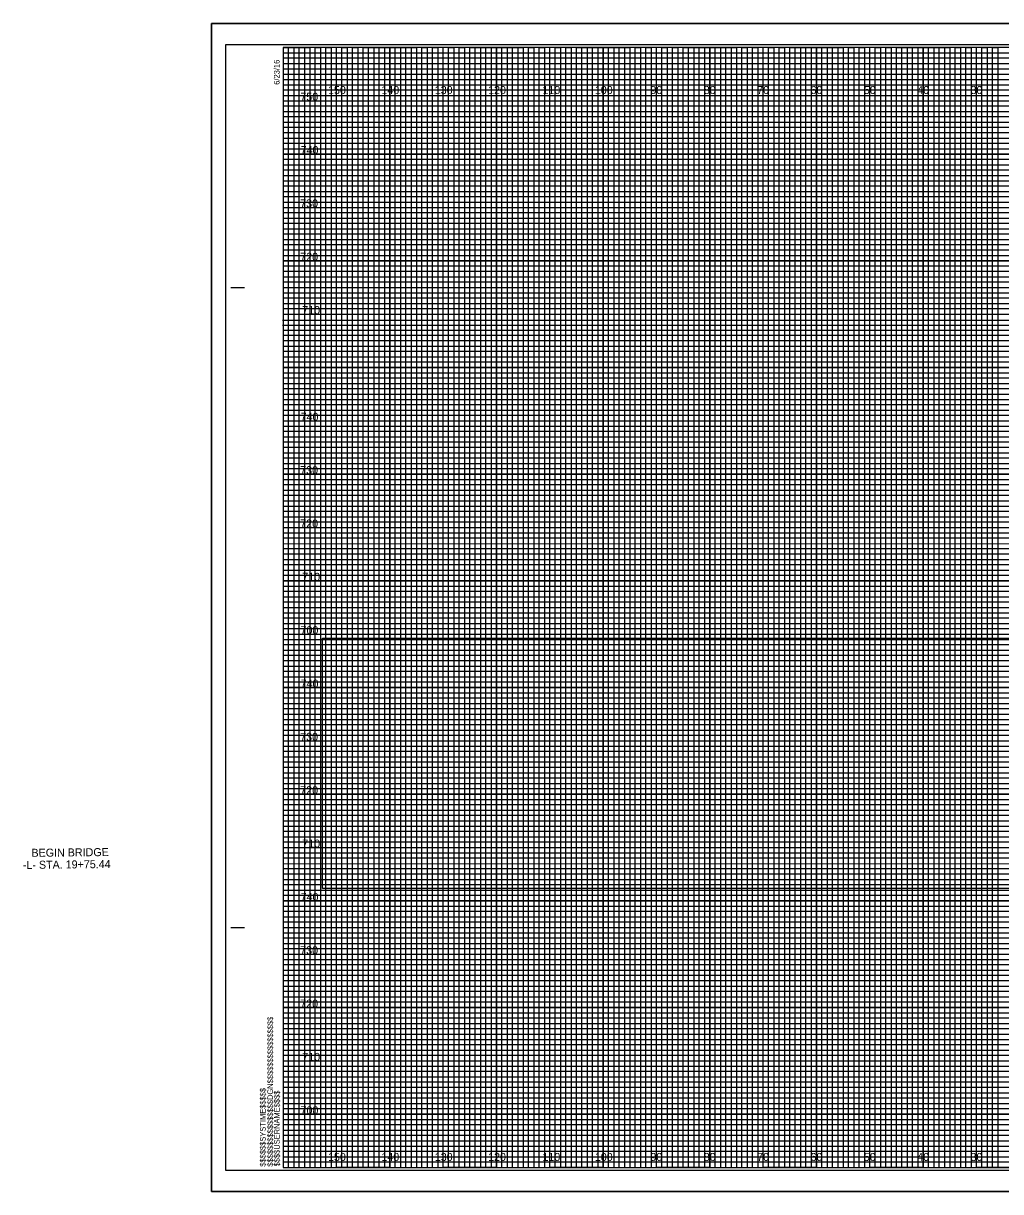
# Model space of a CAD drawing. Extents: x -98 to 717, y -10 to 1974.
# Drawn here: x -48.7 to 134.5, y 875.5 to 1094.5 of the extents above; entities that cross this region are included whole.
import ezdxf

# ---------------------------------------------------------------- set-up
doc = ezdxf.new("R2010")
doc.units = 0
for name, color, linetype in [('Default', 7, 'Continuous'), ('Exist XS Center Line Elevation Label', 7, 'Continuous'), ('Prop CMT Conc Surface', 7, 'Continuous'), ('Prop CMT Concrete Structures', 7, 'Continuous'), ('Prop CMT Pvmt Course 1 CG', 7, 'Continuous'), ('Prop CMT Pvmt Course 2', 7, 'Continuous'), ('Prop CMT Pvmt Course 3', 7, 'Continuous'), ('Prop CMT Pvmt Surface', 7, 'Continuous'), ('Prop CMT Subgrade Earthwork', 7, 'Continuous'), ('Prop XS Ditch Standard Text', 7, 'Continuous'), ('Prop XS Dump Level', 7, 'Continuous'), ('Prop XS Earthwork Shape', 7, 'Continuous'), ('Prop XS Elevation Labels', 7, 'Continuous'), ('Typical Curb CELL', 7, 'Continuous')]:
    doc.layers.add(name, color=color, linetype=linetype)

msp = doc.modelspace()

# ---------------------------------------------------------------- linework, layer by layer
at = {"layer": 'Default'}
msp.add_lwpolyline([(323.3, 875.5), (-13.4, 875.5), (-13.4, 1094.5), (323.3, 1094.5)], close=True, dxfattribs=at)
at = {"layer": 'Exist XS Center Line Elevation Label'}
for p, q in [((0, 1089), (260, 1089)), ((260, 1087.98), (0, 1087.98)), ((0, 1087.98), (0, 1087)), ((0, 1087), (260, 1087)), ((260, 1085.89), (0, 1085.89)), ((0, 1085.89), (0, 1084)), ((0, 1084), (320, 1084))]:
    msp.add_line(p, q, dxfattribs=at)
for points in [[(0, 1083), (270, 1083), (320, 1083), (320, 1082), (0, 1082)], [(0, 1081), (320, 1081), (320, 1079), (0, 1079)], [(0, 1078), (320, 1078), (320, 1077), (0, 1076.98)], [(0, 1076), (320, 1076), (320, 1074), (0, 1074)], [(0, 1073), (320, 1073), (320, 1072), (0, 1072)], [(0, 1071), (320, 1071), (320, 1069), (0, 1069)], [(0, 1068), (320, 1068), (320, 1067), (0, 1067)], [(0, 1066), (320, 1066), (320, 1064), (0, 1064)], [(0, 1063), (320, 1063), (320, 1062), (0, 1062)], [(0, 1061), (320, 1061), (320, 1059), (0, 1059)], [(0, 1058), (320, 1058), (320, 1057), (0, 1057)], [(0, 1056), (320, 1056), (320, 1053.95), (320, 1053), (320, 1052), (0, 1052)], [(0, 1054), (320, 1054), (320, 1053), (0, 1053)], [(0, 1051), (320, 1051), (320, 1049), (0, 1049.03)], [(0, 1049.03), (320, 1049), (320, 1048), (0, 1048)], [(0, 1047), (320, 1047), (320, 1046), (0, 1046)], [(0, 1044), (320, 1044), (320, 1043), (0, 1043)], [(0, 1042), (320, 1042), (320, 1041), (0, 1041)], [(-0.07, 1038.89), (320, 1038.89), (320, 1037.88), (-0.07, 1037.88)], [(0, 1037), (320, 1037), (320, 1036), (0, 1036)], [(0, 1034), (320, 1034), (320, 1033), (0, 1033)], [(0, 1032), (320, 1032), (320, 1031), (0, 1031)], [(0, 1029), (320, 1029), (320, 1028), (0, 1028)], [(0, 1027), (320, 1027), (320, 1026), (0, 1026)], [(0, 1024), (320, 1024), (320, 1023), (0, 1023)], [(0, 1022), (320, 1022), (320, 1021), (0, 1021)], [(0, 1019), (320, 1019), (319.99, 1017.98), (0, 1018)], [(0, 1017), (320, 1017), (320, 1016), (0, 1016)], [(0, 1014), (320, 1014), (320, 1013), (0, 1013)], [(0, 1012), (320, 1012), (320, 1011), (0, 1011)], [(0, 1009), (320, 1009), (320, 1008), (0, 1008)], [(0, 1007), (320, 1007), (320, 1006), (0, 1006)], [(0, 1004), (320, 1004), (320, 1003), (0, 1003)], [(0, 1002), (320, 1002), (320, 1001), (0, 1001)], [(0, 999), (320, 999), (320, 998), (0, 998)], [(0, 996.99), (320.07, 996.91), (320, 996), (0, 996)], [(0, 994), (320, 994), (320, 993), (0, 993)], [(0, 992), (320, 992), (320, 991), (0, 991)], [(0, 989), (320, 989), (320, 988), (0, 988)], [(0, 987), (320, 987), (320, 986), (0, 986)], [(0, 984), (320, 984), (320, 983), (0, 983)], [(0, 982), (320, 982), (320, 981), (0, 981)], [(0, 979), (320, 979), (320, 978), (0, 978)], [(0, 977), (320, 977), (320, 976), (0, 976)], [(0, 974), (320, 974), (320, 973), (0, 973)], [(0, 972), (320, 972), (320, 971), (0, 971)], [(0, 969), (320, 969), (320, 968), (0, 968)], [(0, 967), (320, 967), (320, 966), (0, 966)], [(0, 964), (320, 964), (320, 963), (0, 963)], [(0, 962), (320, 962), (320, 961), (0, 961)], [(0, 959), (320, 959), (319.99, 957.98), (0, 958)], [(0, 957), (320, 957), (320, 956), (0, 956)], [(0, 954), (320, 954), (320, 953), (0, 953)], [(0, 952), (320, 952), (320, 951), (0, 951)], [(0, 949), (320, 949), (320, 948), (0, 948)], [(0, 947), (320, 947), (320, 946), (0, 946)], [(0, 944), (320, 944), (320, 943), (0, 943)], [(0, 942), (320, 942), (320, 941), (0, 941)], [(0, 939), (320, 939), (320, 938), (0, 938)], [(0, 936.99), (320.07, 936.91), (320, 936), (0, 936)], [(0, 934), (320, 934), (320, 933), (0, 933)], [(0, 932), (320, 932), (320, 931), (0, 931)], [(0, 929), (320, 929), (320, 928), (0, 928)], [(0, 927), (320, 927), (320, 926), (0, 926)], [(0, 924), (320, 924), (320, 923), (0, 923)], [(0, 922), (320, 922), (320, 921), (0, 921)], [(0, 919), (320, 919), (320, 918), (0, 918)], [(0, 917), (320, 917), (320, 916), (0, 916)], [(0, 914), (320, 914), (320, 913), (0, 913)], [(0, 912), (320, 912), (320, 911), (0, 911)], [(0, 909), (320, 909), (320, 908), (0, 908)], [(0, 907), (320, 907), (320, 906), (0, 906)], [(0, 904), (320, 904), (320, 903), (0, 903)], [(0, 902), (320, 902), (320, 901), (0, 901)], [(0, 899), (320, 899), (320, 898), (0, 898)], [(0, 897), (320, 897), (320, 896), (0, 896)], [(0, 894), (320, 894), (320, 893), (0, 893)], [(0, 892), (320, 892), (320, 891), (0, 891)], [(0, 889), (320, 889), (320, 888), (0, 888)], [(0, 887), (320, 887), (320, 886), (0, 886)], [(0, 884), (320, 884), (320, 883), (0, 883)], [(0, 882), (320, 882), (320, 881), (0, 881)]]:
    msp.add_lwpolyline(points, dxfattribs=at)
at = {"layer": 'Prop CMT Conc Surface'}
for p, q in [((-9.8, 1045), (-7.3, 1045)), ((-9.7, 1045), (-7.2, 1045)), ((-9.8, 925), (-7.3, 925)), ((-9.7, 925), (-7.2, 925)), ((0, 880), (0, 880)), ((0, 880), (0, 880)), ((0, 880), (0, 880)), ((0, 880), (0, 880)), ((0, 880), (0, 880)), ((0, 880), (0, 880)), ((0, 880), (0, 880))]:
    msp.add_line(p, q, dxfattribs=at)
msp.add_lwpolyline([(320, 1090), (0, 1090), (0, 880), (320, 880)], close=True, dxfattribs=at)
at = {"layer": 'Prop CMT Concrete Structures'}
for p, q in [((10, 880), (10, 1090)), ((20, 880), (20, 1090)), ((30, 880), (30, 1090)), ((40, 880), (40, 1090)), ((50, 880), (50, 1090)), ((60, 880), (60, 1090)), ((70, 880), (70, 1090)), ((80, 880), (80, 1090)), ((90, 880), (90, 1090)), ((100, 880), (100, 1090)), ((110, 880), (110, 1090)), ((120, 880), (120, 1090)), ((130, 880), (130, 1090)), ((0, 1080), (320, 1080)), ((0, 1070), (320, 1070)), ((0, 1060), (320, 1060)), ((0, 1050), (320, 1050)), ((0, 1040), (320, 1040)), ((0, 1030), (320, 1030)), ((0, 1020), (320, 1020)), ((0, 1010), (320, 1010)), ((0, 1000), (320, 1000)), ((0, 990), (320, 990)), ((0, 980), (320, 980)), ((0, 970), (320, 970)), ((0, 960), (320, 960)), ((0, 950), (320, 950)), ((0, 940), (320, 940)), ((0, 930), (320, 930)), ((0, 920), (320, 920)), ((0, 910), (320, 910)), ((0, 900), (320, 900)), ((0, 890), (320, 890))]:
    msp.add_line(p, q, dxfattribs=at)
at = {"layer": 'Prop CMT Pvmt Course 2'}
msp.add_lwpolyline([(-13.4, 875.5), (323.3, 875.5), (323.3, 1094.5), (-13.4, 1094.5)], close=True, dxfattribs=at)
at = {"layer": 'Prop CMT Pvmt Course 3'}
msp.add_lwpolyline([(-10.8, 879.5), (322.4, 879.5), (322.4, 1090.5), (-10.8, 1090.5)], close=True, dxfattribs=at)
at = {"layer": 'Prop CMT Pvmt Surface'}
for p, q in [((323.3, 1094.5), (-13.4, 1094.5)), ((-13.4, 1094.5), (-13.4, 875.5)), ((-13.4, 875.5), (323.3, 875.5))]:
    msp.add_line(p, q, dxfattribs=at)
at = {"layer": 'Prop CMT Subgrade Earthwork'}
for points in [[(0, 880), (1, 880), (1, 1090), (2, 1090), (2, 880)], [(2, 880), (3, 880), (3, 1090), (4, 1090), (4, 880)], [(5, 880), (6, 880), (6, 1090), (7, 1090), (7, 880)], [(7, 880), (8, 880), (8, 1090), (9, 1090), (9, 880)], [(10, 880), (11, 880), (11, 1090), (12, 1090), (12, 880)], [(12, 880), (13, 880), (13, 1090), (14, 1090), (14, 880)], [(15, 880), (16, 880), (16, 1090), (17, 1090), (17, 880)], [(17, 880), (18, 880), (18, 1090), (19, 1090), (19, 880)], [(20, 880), (21, 880), (21, 1090), (22, 1090), (22, 880)], [(22, 880), (23, 880), (23, 1090), (24, 1090), (24, 880)], [(25, 880), (26, 880), (26, 1090), (27, 1090), (27, 880)], [(27, 880), (28, 880), (28, 1090), (29, 1090), (29, 880)], [(30, 880), (31, 880), (31, 1090), (32, 1090), (32, 880)], [(32, 880), (33, 880), (33, 1090), (34, 1090), (34, 880)], [(35, 880), (36, 880), (36, 1090), (37, 1090), (37, 880)], [(37, 880), (38, 880), (38, 1090), (39, 1090), (39, 880)], [(40, 880), (41, 880), (41, 1090), (42, 1090), (42, 880)], [(42, 880), (43, 880), (43, 1090), (44, 1090), (44, 880)], [(45, 880), (46, 880), (46, 1090), (47, 1090), (47, 880)], [(47, 880), (48, 880), (48, 1090), (49, 1090), (49, 880)], [(50, 880), (51, 880), (51, 1090), (52, 1090), (52, 880)], [(52, 880), (53, 880), (53, 1090), (54, 1090), (54, 880)], [(55, 880), (56, 880), (56, 1090), (57, 1090), (57, 880)], [(57, 880), (58, 880), (58, 1090), (59, 1090), (59, 880)], [(60, 880), (61, 880), (61, 1090), (62, 1090), (62, 880)], [(62, 880), (63, 880), (63, 1090), (64, 1090), (64, 880)], [(65, 880), (66, 880), (66, 1090), (67, 1090), (67, 880)], [(67, 880), (68, 880), (68, 1090), (69, 1090), (69, 880)], [(70, 880), (71, 880), (71, 1090), (72, 1090), (72, 880)], [(72, 880), (73, 880), (73, 1090), (74, 1090), (74, 880)], [(75, 880), (76, 880), (76, 1090), (77, 1090), (77, 880)], [(77, 880), (78, 880), (78, 1090), (79, 1090), (79, 880)], [(80, 880), (81, 880), (81, 1090), (82, 1090), (82, 880)], [(82, 880), (83, 880), (83, 1090), (84, 1090), (84, 880)], [(85, 880), (86, 880), (86, 1090), (87, 1090), (87, 880)], [(87, 880), (88, 880), (88, 1090), (89, 1090), (89, 880)], [(90, 880), (91, 880), (91, 1090), (92, 1090), (92, 880)], [(92, 880), (93, 880), (93, 1090), (94, 1090), (94, 880)], [(95, 880), (96, 880), (96, 1090), (97, 1090), (97, 880)], [(97, 880), (98, 880), (98, 1090), (99, 1090), (99, 880)], [(100, 880), (101, 880), (101, 1090), (102, 1090), (102, 880)], [(102, 880), (103, 880), (103, 1090), (104, 1090), (104, 880)], [(105, 880), (106, 880), (106, 1090), (107, 1090), (107, 880)], [(107, 880), (108, 880), (108, 1090), (109, 1090), (109, 880)], [(110, 880), (111, 880), (111, 1090), (112, 1090), (112, 880)], [(112, 880), (113, 880), (113, 1090), (114, 1090), (114, 880)], [(115, 880), (116, 880), (116, 1090), (117, 1090), (117, 880)], [(117, 880), (118, 880), (118, 1090), (119, 1090), (119, 880)], [(120, 880), (121, 880), (121, 1090), (122, 1090), (122, 880)], [(122, 880), (123, 880), (123, 1090), (124, 1090), (124, 880)], [(125, 880), (126, 880), (126, 1090), (127, 1090), (127, 880)], [(127, 880), (128, 880), (128, 1090), (129, 1090), (129, 880)], [(130, 880), (131, 880), (131, 1090), (132, 1090), (132, 880)], [(132, 880), (133, 880), (133, 1090), (134, 1090), (134, 880)]]:
    msp.add_lwpolyline(points, dxfattribs=at)
at = {"layer": 'Prop XS Ditch Standard Text'}
msp.add_lwpolyline([(7.42, 979.26), (318.51, 979.26), (318.51, 932.35), (7.42, 932.35)], close=True, dxfattribs=at)
at = {"layer": 'Prop XS Elevation Labels'}
for p, q in [((10, 1090), (0, 1090)), ((10, 880), (10, 1090)), ((30, 1090), (20, 1090)), ((20, 1090), (20, 880)), ((30, 880), (30, 1090)), ((50, 1090), (40, 1090)), ((40, 1090), (40, 880)), ((50, 880), (50, 1090)), ((70, 1090), (60, 1090)), ((60, 1090), (60, 880)), ((70, 880), (70, 1090)), ((90, 1090), (80, 1090)), ((80, 1090), (80, 880)), ((90, 880), (90, 1090)), ((110, 1090), (100, 1090)), ((100, 1090), (100, 880)), ((110, 880), (110, 1090)), ((130, 1090), (120, 1090)), ((120, 1090), (120, 880)), ((130, 880), (130, 1090)), ((20, 880), (10, 880)), ((40, 880), (30, 880)), ((60, 880), (50, 880)), ((80, 880), (70, 880)), ((100, 880), (90, 880)), ((120, 880), (110, 880)), ((140, 880), (130, 880))]:
    msp.add_line(p, q, dxfattribs=at)
for points in [[(0, 1080), (320, 1080), (320, 1070), (0, 1070)], [(0, 1060), (320, 1060), (320, 1050), (0, 1050)], [(0, 1040), (320, 1040), (320, 1030), (0, 1030)], [(0, 1020), (320, 1020), (320, 1010), (0, 1010)], [(0, 1000), (320, 1000), (320, 990), (0, 990)], [(0, 980), (320, 980), (320, 970), (0, 970)], [(0, 960), (320, 960), (320, 950), (0, 950)], [(0, 940), (320, 940), (320, 930), (0, 930)], [(0, 920), (320, 920), (320, 910), (0, 910)], [(0, 900), (320, 900), (320, 890), (0, 890)]]:
    msp.add_lwpolyline(points, dxfattribs=at)
at = {"layer": 'Typical Curb CELL'}
for points in [[(0, 1090), (5, 1090), (5, 880), (15, 880), (15, 1090), (25, 1090), (25, 880), (35, 880), (35, 1090), (45, 1090), (45, 880), (55, 880), (55, 1090), (65, 1090), (65, 880), (75, 880), (75, 1090), (85, 1090), (85, 880), (95, 880), (95, 1090), (105, 1090), (105, 880), (115, 880), (115, 1090), (125, 1090), (125, 880), (135, 880)], [(0, 1085), (275, 1085)], [(0, 1065), (320, 1065), (320, 1075), (0, 1075)], [(0, 1045), (320, 1045), (320, 1055), (0, 1055)], [(0, 1025), (320, 1025), (320, 1035), (0, 1035)], [(0, 1005), (320, 1005), (320, 1015), (0, 1015)], [(0, 985), (320, 985), (320, 995), (0, 995)], [(0, 965), (320, 965), (320, 975), (0, 975)], [(0, 945), (320, 945), (320, 955), (0, 955)], [(0, 925), (320, 925), (320, 935), (0, 935)], [(0, 905), (320, 905), (320, 915), (0, 915)], [(0, 885), (320, 885), (320, 895), (0, 895)]]:
    msp.add_lwpolyline(points, dxfattribs=at)

# ---------------------------------------------------------------- texts
at = {"layer": 'Prop CMT Conc Surface'}
for s, p in [('6/23/16', (-0.65, 1083)), ('$$$$$$$$$$$$$$$$DGN$$$$$$$$$$$$$$$$', (-1.88, 880.18)), ('$$$$$$SYSTIME$$$$$', (-3.26, 880.18)), ('$$$$USERNAME$$$$', (-0.62, 880.23))]:
    msp.add_text(s, height=1.05, rotation=90, dxfattribs=at).set_placement(p)
at = {"layer": 'Prop CMT Pvmt Course 1 CG'}
for s, p in [('750', (3.25, 1080)), ('740', (3.3, 1070)), ('730', (3.22, 1060)), ('720', (3.23, 1050)), ('710', (3.61, 1040)), ('740', (3.3, 1020)), ('730', (3.22, 1010)), ('720', (3.23, 1000)), ('710', (3.61, 990)), ('700', (3.28, 980)), ('740', (3.3, 970)), ('730', (3.22, 960)), ('720', (3.23, 950)), ('710', (3.61, 940)), ('740', (3.3, 930)), ('730', (3.22, 920)), ('720', (3.23, 910)), ('710', (3.61, 900)), ('700', (3.28, 890))]:
    msp.add_text(s, height=1.5, dxfattribs=at).set_placement(p)
at = {"layer": 'Prop XS Dump Level'}
for s, p in [('BEGIN BRIDGE', (-47.14, 938.26)), ('-L- STA. 19+75.44', (-48.75, 935.99))]:
    msp.add_text(s, height=1.5, rotation=0.5926, dxfattribs=at).set_placement(p)
at = {"layer": 'Prop XS Earthwork Shape'}
for s, p in [('150', (8.44, 1081.25)), ('140', (18.44, 1081.25)), ('130', (28.44, 1081.25)), ('120', (38.44, 1081.25)), ('110', (48.62, 1081.25)), ('100', (58.44, 1081.25)), ('90', (68.86, 1081.25)), ('80', (78.86, 1081.25)), ('70', (88.86, 1081.25)), ('60', (98.86, 1081.25)), ('50', (108.86, 1081.25)), ('40', (118.86, 1081.25)), ('30', (128.86, 1081.25)), ('150', (8.44, 881.25)), ('140', (18.44, 881.25)), ('130', (28.44, 881.25)), ('120', (38.44, 881.25)), ('110', (48.62, 881.25)), ('100', (58.44, 881.25)), ('90', (68.86, 881.25)), ('80', (78.86, 881.25)), ('70', (88.86, 881.25)), ('60', (98.86, 881.25)), ('50', (108.86, 881.25)), ('40', (118.86, 881.25)), ('30', (128.86, 881.25))]:
    msp.add_text(s, height=1.5, dxfattribs=at).set_placement(p)

doc.saveas('drawing.dxf')
